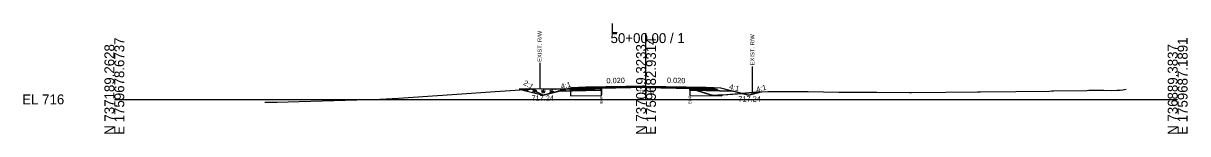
# Model space of a CAD drawing. Extents: x -26 to 4303, y -10 to 9577.
# Drawn here: x 3974.3 to 4302.8, y -9.7 to 21.5 of the extents above; entities that cross this region are included whole.
import ezdxf

# ---------------------------------------------------------------- set-up
doc = ezdxf.new("R2010")
doc.units = 0
for name, color, linetype in [('Default', 7, 'Continuous'), ('Exist CMT Pavement', 7, 'Continuous'), ('Old_Level_2', 7, 'Continuous'), ('Pattern 3', 7, 'Continuous'), ('Prop CMT Conc Surface', 7, 'Continuous'), ('Prop CMT Concrete Structures', 7, 'Continuous'), ('Prop CMT Pvmt Course 1', 7, 'Continuous'), ('Prop CMT Pvmt Course 1 CG', 7, 'Continuous'), ('Prop CMT Pvmt Course 2', 7, 'Continuous'), ('Prop CMT Pvmt Course 2 Wedge', 7, 'Continuous'), ('Prop CMT Pvmt Course 3', 7, 'Continuous'), ('Prop CMT Pvmt Surface', 7, 'Continuous'), ('Prop CMT Pvmt Surface Shoulder', 7, 'Continuous'), ('Prop CMT Pvmt Wedge Surface 1', 7, 'Continuous'), ('Prop CMT Pvmt Wedge Surface 2', 7, 'Continuous'), ('Prop CMT Pvmt Wedge Surface 3', 7, 'Continuous'), ('Prop CMT Shld Paved Course 1', 7, 'Continuous'), ('Prop CMT Shld Paved Course 2', 7, 'Continuous'), ('Prop CMT Shld Paved Course 3', 7, 'Continuous'), ('Prop CMT Slope Grass', 7, 'Continuous'), ('Prop CMT Subgrade Earthwork', 7, 'Continuous'), ('Prop Road Sect_ Recs - UC Shallow (Outline)', 7, 'Continuous'), ('Prop Shade Light', 7, 'Continuous'), ('Prop XS DDE Elevations', 7, 'Continuous'), ('Prop XS Ditch Standard Text', 7, 'Continuous'), ('Prop XS Hydro Elevations', 7, 'Continuous'), ('Prop XS SE Text', 7, 'Continuous'), ('Prop XS Side Slope Text', 7, 'Continuous'), ('Prop XS Wedging', 7, 'Continuous'), ('Scratch_Level_2', 7, 'Continuous')]:
    doc.layers.add(name, color=color, linetype=linetype)

msp = doc.modelspace()

# ---------------------------------------------------------------- linework, layer by layer
at = {"layer": 'Exist CMT Pavement'}
for points in [[(4150, 3.78), (4133, 3.44)], [(4150, 3.78), (4167, 3.44)]]:
    msp.add_lwpolyline(points, dxfattribs=at)
at = {"layer": 'Old_Level_2'}
for p, q in [((4150, 0), (4150, 18.71)), ((4150, 0), (4150, 18.71)), ((4000, 0), (4150, 0)), ((4150, 0), (4300, 0)), ((4000, 0), (4150, 0)), ((4150, 0), (4300, 0))]:
    msp.add_line(p, q, dxfattribs=at)
at = {"layer": 'Pattern 3'}
for p, q in [((4115.87, 2.95), (4116.45, 2.37)), ((4116.04, 2.47), (4116.88, 2.7)), ((4116.39, 2.96), (4116.25, 2.42)), ((4118.03, 2.26), (4119.24, 2.58)), ((4118.2, 2.86), (4119.08, 1.98)), ((4118.77, 2.91), (4118.49, 1.86)), ((4120.04, 1.79), (4119.96, 1.5)), ((4120.39, 2.14), (4121.6, 2.46)), ((4120.55, 2.74), (4121.44, 1.86)), ((4121.14, 2.86), (4120.83, 1.7)), ((4121.79, 1.51), (4121.85, 1.45)), ((4121.96, 2.85), (4121.95, 2.82)), ((4122.39, 1.67), (4122.37, 1.58)), ((4122.75, 2.02), (4123.95, 2.35)), ((4122.91, 2.63), (4123.64, 1.9)), ((4123.51, 2.79), (4123.25, 1.8)), ((4124.35, 2.84), (4124.31, 2.7)), ((4125.26, 2.51), (4125.43, 2.34)), ((4125.87, 2.67), (4125.81, 2.44)), ((4126.73, 2.83), (4126.68, 2.66)), ((4127.18, 2.83), (4127.22, 2.79)), ((4177.37, 1.72), (4177.47, 1.62)), ((4177.92, 1.76), (4177.85, 1.52)), ((4178.26, 1.42), (4178.4, 1.46)), ((4178.76, 1.83), (4178.75, 1.81)), ((4179.71, 1.62), (4179.87, 1.45)), ((4180.31, 1.78), (4180.25, 1.55)), ((4181.19, 2.01), (4181.13, 1.77)), ((4181.53, 2.04), (4181.66, 1.9))]:
    msp.add_line(p, q, dxfattribs=at)
for points in [[(4137.42, 3.3), (4137.41, 2.65), (4128.69, 2.47), (4128.68, 2.83), (4130.46, 2.82), (4131.03, 2.85), (4132.25, 2.92), (4134.24, 3.03), (4135.83, 3.13), (4137.42, 3.3)], [(4114.24, 2.93), (4121, 1.24), (4127.38, 2.83), (4121.38, 2.86), (4116.36, 2.96)], [(4162.41, 3.17), (4162.41, 2.65), (4164.13, 2.62)], [(4182.47, 2.1), (4179, 1.24), (4177.13, 1.7), (4180.99, 2)]]:
    msp.add_lwpolyline(points, close=True, dxfattribs=at)
at = {"layer": 'Prop CMT Conc Surface'}
for points in [[(4137.41, 3.27), (4133, 3.19)], [(4133, 3.19), (4133, 2.98)], [(4133, 2.98), (4137.41, 3.07)], [(4137.41, 3.07), (4137.41, 3.27)], [(4162.41, 3.07), (4162.41, 3.28)], [(4162.41, 3.28), (4167, 3.19)], [(4167, 2.98), (4162.41, 3.07)], [(4167, 3.19), (4167, 2.98)]]:
    msp.add_lwpolyline(points, dxfattribs=at)
at = {"layer": 'Prop CMT Concrete Structures'}
for points in [[(4133, 3.19), (4133, 3.44)], [(4150, 3.65), (4137.41, 3.4)], [(4137.41, 3.4), (4137.41, 3.27)], [(4150, 3.65), (4162.41, 3.4)], [(4162.41, 3.4), (4162.41, 3.28)], [(4167, 3.19), (4167, 3.44)], [(4137.41, 3.27), (4133, 3.19)], [(4162.41, 3.28), (4167, 3.19)]]:
    msp.add_lwpolyline(points, dxfattribs=at)
at = {"layer": 'Prop CMT Pvmt Course 1'}
for points in [[(4137.41, 3.07), (4133, 2.98)], [(4133, 2.98), (4133, 2.64)], [(4133, 2.64), (4137.41, 2.73)], [(4137.41, 2.73), (4137.41, 3.07)], [(4162.41, 3.07), (4167, 2.98)], [(4162.41, 2.74), (4162.41, 3.07)], [(4167, 2.64), (4162.41, 2.74)], [(4167, 2.98), (4167, 2.64)]]:
    msp.add_lwpolyline(points, dxfattribs=at)
at = {"layer": 'Prop CMT Pvmt Course 2'}
for points in [[(4133, 3.44), (4131, 3.4), (4130.74, 3.14)], [(4133, 3.19), (4133, 3.44)], [(4167, 3.44), (4169, 3.4), (4169.26, 3.14)], [(4167, 3.19), (4167, 3.44)], [(4130.74, 3.14), (4133, 3.19)], [(4169.26, 3.14), (4167, 3.19)]]:
    msp.add_lwpolyline(points, dxfattribs=at)
at = {"layer": 'Prop CMT Pvmt Course 2 Wedge'}
msp.add_line((4117.68, 2.9), (4121, 1.24), dxfattribs=at)
for points in [[(4131, 3.4), (4129, 3.24), (4121, 1.24)], [(4169, 3.4), (4171, 3.24), (4179, 1.24), (4182.47, 2.1)]]:
    msp.add_lwpolyline(points, dxfattribs=at)
at = {"layer": 'Prop CMT Pvmt Course 3'}
for points in [[(4133, 3.19), (4130.74, 3.14), (4130.53, 2.93)], [(4130.53, 2.93), (4133, 2.98)], [(4133, 2.98), (4133, 3.19)], [(4167, 3.19), (4169.26, 3.14), (4169.47, 2.93)], [(4167, 2.98), (4167, 3.19)], [(4169.47, 2.93), (4167, 2.98)]]:
    msp.add_lwpolyline(points, dxfattribs=at)
at = {"layer": 'Prop CMT Pvmt Surface'}
for points in [[(4150, 3.53), (4133, 3.19)], [(4133, 3.19), (4133, 3.44)], [(4150, 3.53), (4167, 3.19)], [(4167, 3.19), (4167, 3.44)]]:
    msp.add_lwpolyline(points, dxfattribs=at)
at = {"layer": 'Prop CMT Pvmt Surface Shoulder'}
for points in [[(4137.42, 3.3), (4137.44, 3.3), (4137.93, 3.32), (4138.07, 3.32), (4138.18, 3.34), (4138.84, 3.35), (4140.18, 3.39), (4140.57, 3.4), (4141.63, 3.42), (4143.07, 3.44), (4144.06, 3.47), (4145.57, 3.53), (4146.49, 3.54), (4148.07, 3.56), (4148.38, 3.57), (4148.89, 3.57), (4149.15, 3.57), (4149.86, 3.58), (4150, 3.58)], [(4150, 3.58), (4150.31, 3.59), (4150.48, 3.59), (4150.57, 3.59), (4151.35, 3.57), (4153.07, 3.54), (4153.79, 3.52), (4155.58, 3.47), (4156.22, 3.45), (4158.08, 3.4), (4158.74, 3.38), (4159.85, 3.34), (4160.97, 3.3), (4161.48, 3.27), (4162.26, 3.22), (4162.41, 3.17)]]:
    msp.add_lwpolyline(points, dxfattribs=at)
at = {"layer": 'Prop CMT Pvmt Wedge Surface 1'}
for p, q in [((4133.02, 2.52), (4125.53, 2.37)), ((4137.41, 2.61), (4133.02, 2.52)), ((4162.41, 2.61), (4166.98, 2.52)), ((4166.98, 2.52), (4174.47, 2.37))]:
    msp.add_line(p, q, dxfattribs=at)
for points in [[(4137.41, 2.61), (4137.42, 3.3)], [(4162.41, 2.61), (4162.41, 3.17)]]:
    msp.add_lwpolyline(points, dxfattribs=at)
at = {"layer": 'Prop CMT Pvmt Wedge Surface 2'}
for points in [[(4137.41, 3.4), (4137.44, 3.4), (4137.93, 3.41), (4138.07, 3.41), (4138.18, 3.41), (4138.84, 3.43), (4140.18, 3.45), (4140.57, 3.46), (4141.63, 3.48), (4143.07, 3.51), (4144.06, 3.53), (4145.57, 3.56), (4146.49, 3.58), (4148.07, 3.61), (4148.38, 3.62), (4148.89, 3.63), (4149.15, 3.63), (4149.86, 3.65), (4150, 3.65)], [(4150, 3.58), (4149.86, 3.58), (4149.15, 3.57), (4148.89, 3.57), (4148.38, 3.57), (4148.07, 3.56), (4146.49, 3.54), (4145.57, 3.53), (4144.06, 3.47), (4143.07, 3.44), (4141.63, 3.42), (4140.57, 3.4), (4140.18, 3.39), (4138.84, 3.35), (4138.18, 3.34), (4138.07, 3.32), (4137.93, 3.32), (4137.44, 3.3), (4137.41, 3.3)], [(4137.41, 3.3), (4137.41, 3.4)], [(4150, 3.65), (4150, 3.58)], [(4150, 3.65), (4150.31, 3.64), (4150.48, 3.64), (4150.57, 3.64), (4151.35, 3.62), (4153.07, 3.59), (4153.79, 3.57), (4155.58, 3.54), (4156.22, 3.53), (4158.08, 3.49), (4158.74, 3.48), (4159.85, 3.45), (4160.97, 3.43), (4161.48, 3.42), (4162.26, 3.41), (4162.41, 3.4)], [(4162.41, 3.28), (4162.26, 3.28), (4161.48, 3.3), (4160.97, 3.31), (4160.9, 3.31), (4159.85, 3.34), (4158.74, 3.38), (4158.08, 3.4), (4156.22, 3.45), (4155.58, 3.47), (4153.79, 3.52), (4153.07, 3.54), (4151.35, 3.57), (4150.57, 3.59), (4150.48, 3.59), (4150.31, 3.59), (4150, 3.58)], [(4162.41, 3.4), (4162.41, 3.28)]]:
    msp.add_lwpolyline(points, dxfattribs=at)
at = {"layer": 'Prop CMT Pvmt Wedge Surface 3'}
for points in [[(4162.41, 3.17), (4162.26, 3.22), (4161.48, 3.27), (4160.97, 3.3), (4160.9, 3.31)], [(4160.9, 3.31), (4160.97, 3.31)], [(4160.97, 3.31), (4161.48, 3.3), (4162.26, 3.28), (4162.41, 3.28)], [(4162.41, 3.28), (4162.41, 3.17)]]:
    msp.add_lwpolyline(points, dxfattribs=at)
at = {"layer": 'Prop CMT Shld Paved Course 1'}
for points in [[(4133, 2.98), (4133, 3.44)], [(4150, 3.32), (4133, 2.98)], [(4150, 3.32), (4167, 2.98)], [(4167, 2.98), (4167, 3.44)]]:
    msp.add_lwpolyline(points, dxfattribs=at)
at = {"layer": 'Prop CMT Shld Paved Course 2'}
for points in [[(4133, 3.44), (4131, 3.4)], [(4167, 3.44), (4169, 3.4)]]:
    msp.add_lwpolyline(points, dxfattribs=at)
at = {"layer": 'Prop CMT Shld Paved Course 3'}
for points in [[(4150, 3.78), (4133, 3.44)], [(4133, 3.44), (4133, 3.19)], [(4137.41, 3.4), (4150, 3.65)], [(4137.41, 3.27), (4137.41, 3.4)], [(4150, 3.53), (4150, 3.78)], [(4150, 3.78), (4167, 3.44)], [(4150, 3.65), (4150, 3.53), (4150, 3.53)], [(4162.41, 3.4), (4150, 3.65)], [(4162.41, 3.28), (4162.41, 3.4)], [(4167, 3.44), (4167, 3.19)], [(4133, 3.19), (4137.41, 3.27)], [(4167, 3.19), (4162.41, 3.28)]]:
    msp.add_lwpolyline(points, dxfattribs=at)
at = {"layer": 'Prop CMT Slope Grass'}
msp.add_lwpolyline([(4042.46, -0.8), (4045.91, -0.76), (4052.14, -0.57), (4074.87, 0.11), (4080.19, 0.34), (4084.27, 0.61), (4098.02, 1.59), (4106.01, 2.1), (4120.16, 3.07), (4125.39, 3.01), (4132.53, 3.03), (4137.44, 3.3), (4138.18, 3.34), (4138.84, 3.35), (4140.18, 3.39), (4140.57, 3.4), (4141.63, 3.42), (4143.07, 3.44), (4144.06, 3.47), (4145.57, 3.53), (4146.49, 3.54), (4148.07, 3.56), (4148.38, 3.57), (4149.15, 3.57), (4149.86, 3.58), (4150.57, 3.59), (4151.35, 3.57), (4153.07, 3.54), (4153.79, 3.52), (4155.58, 3.47), (4156.22, 3.45), (4158.08, 3.4), (4158.74, 3.38), (4159.85, 3.34), (4160.97, 3.3), (4161.48, 3.27), (4162.26, 3.22), (4168.19, 1.32), (4169.12, 1.08), (4180.99, 2), (4184.35, 2.24), (4185.99, 2.21), (4194.36, 2.28), (4195.72, 2.24), (4204.36, 2.02), (4213.52, 2.07), (4214.37, 2.06), (4215.17, 2.06), (4224.37, 1.94), (4224.9, 1.93), (4234.63, 2.09), (4243.57, 2.1), (4244.41, 2.1), (4254.39, 2.24), (4263.82, 2.37), (4264.39, 2.38), (4265, 2.39), (4274.4, 2.56), (4274.95, 2.58), (4279.19, 2.58), (4281.45, 2.54), (4282.86, 2.57), (4283.82, 2.57), (4284.51, 2.7), (4285.04, 2.79), (4285.46, 2.89)], dxfattribs=at)
at = {"layer": 'Prop CMT Subgrade Earthwork'}
for points in [[(4133, 2.98), (4130.53, 2.93), (4130.03, 2.92), (4129.69, 2.58)], [(4129.69, 2.58), (4133, 2.64)], [(4133, 2.64), (4133, 2.98)], [(4167, 2.98), (4169.47, 2.93), (4169.97, 2.92), (4170.31, 2.58)], [(4167, 2.64), (4167, 2.98)], [(4170.31, 2.58), (4167, 2.64)]]:
    msp.add_lwpolyline(points, dxfattribs=at)
at = {"layer": 'Prop Road Sect_ Recs - UC Shallow (Outline)'}
for points in [[(4128.72, 0.97), (4137.44, 1.15), (4137.41, 2.64), (4128.69, 2.47)], [(4162.38, 1.15), (4171.36, 0.97), (4171.37, 1.26), (4169.14, 1.09), (4168.19, 1.32), (4164.13, 2.62), (4162.41, 2.65)]]:
    msp.add_lwpolyline(points, close=True, dxfattribs=at)
at = {"layer": 'Prop Shade Light'}
for p, q in [((4129.69, 2.49), (4128.69, 2.47)), ((4128.69, 2.47), (4128.72, 0.97)), ((4128.72, 0.97), (4137.44, 1.15)), ((4137.44, 1.15), (4137.41, 2.65)), ((4162.41, 2.65), (4162.38, 1.15)), ((4162.38, 1.15), (4171.36, 0.97)), ((4164.13, 2.62), (4164.13, 2.62)), ((4171.37, 1.26), (4170.26, 1.17)), ((4171.36, 0.97), (4171.37, 1.26))]:
    msp.add_line(p, q, dxfattribs=at)
for points in [[(4137.41, 2.65), (4133, 2.56), (4129.69, 2.49)], [(4164.13, 2.62), (4164.13, 2.62), (4162.41, 2.65)], [(4170.26, 1.17), (4169.14, 1.09), (4168.19, 1.32), (4164.13, 2.62)]]:
    msp.add_lwpolyline(points, dxfattribs=at)
at = {"layer": 'Prop XS DDE Elevations'}
for points in [[(4128.12, 3.02), (4125.53, 2.37), (4133.02, 2.52), (4137.41, 2.61), (4137.42, 3.3), (4132.53, 3.03)], [(4138.07, 3.32), (4138.18, 3.34), (4137.44, 3.3), (4137.93, 3.32)], [(4148.38, 3.57), (4149.15, 3.57), (4148.89, 3.57)], [(4149.86, 3.58), (4150.57, 3.59), (4150.48, 3.59), (4150.31, 3.59), (4150, 3.58)], [(4128.12, 3.02), (4125.53, 2.37), (4121, 1.24), (4117.68, 2.9), (4120.16, 3.07), (4125.39, 3.01)], [(4162.41, 2.61), (4162.41, 3.17), (4164.27, 2.57)], [(4168.19, 1.32), (4169.12, 1.08), (4177.13, 1.7), (4174.47, 2.37), (4166.98, 2.52), (4164.27, 2.57)], [(4177.13, 1.7), (4179, 1.24), (4182.47, 2.1), (4180.99, 2)]]:
    msp.add_lwpolyline(points, close=True, dxfattribs=at)
at = {"layer": 'Prop XS Ditch Standard Text'}
for p, q in [((4120, 10.29), (4120, 2.89)), ((4180, 9.32), (4180, 1.92)), ((4137.41, 3.3), (4137.41, 1.25)), ((4162.41, 3.17), (4162.41, 1.12))]:
    msp.add_line(p, q, dxfattribs=at)
at = {"layer": 'Prop XS Wedging'}
for p, q in [((4137.42, 3.3), (4137.42, 3.64)), ((4137.42, 3.4), (4137.42, 3.3)), ((4162.41, 3.17), (4162.41, 3.52)), ((4162.41, 3.17), (4162.41, 3.4)), ((4162.41, 3.17), (4162.41, 3.17))]:
    msp.add_line(p, q, dxfattribs=at)
for points in [[(4150, 3.65), (4133, 3.31)], [(4150, 3.65), (4150, 3.65), (4137.42, 3.4)], [(4137.42, 3.3), (4137.44, 3.3), (4138.18, 3.34), (4138.84, 3.35), (4140.18, 3.39), (4140.57, 3.4), (4141.63, 3.42), (4143.07, 3.44), (4144.06, 3.47), (4145.57, 3.53), (4146.49, 3.54), (4148.07, 3.56), (4148.38, 3.57), (4149.15, 3.57), (4149.86, 3.58), (4150.57, 3.59), (4151.35, 3.57), (4153.07, 3.54), (4153.79, 3.52), (4155.58, 3.47), (4156.22, 3.45), (4158.08, 3.4), (4158.74, 3.38), (4159.85, 3.34), (4160.97, 3.3), (4161.48, 3.27), (4162.26, 3.22), (4162.41, 3.17)], [(4150, 3.65), (4167, 3.31)], [(4162.41, 3.4), (4150, 3.65), (4150, 3.65)]]:
    msp.add_lwpolyline(points, dxfattribs=at)
at = {"layer": 'Scratch_Level_2'}
for p, q in [((4130.19, 2.82), (4130.13, 2.59)), ((4130.53, 2.82), (4130.71, 2.64)), ((4132.02, 2.8), (4132.5, 2.94)), ((4132.61, 2.94), (4132.53, 2.63)), ((4132.64, 2.94), (4132.94, 2.64)), ((4134.37, 2.69), (4135.58, 3.01)), ((4134.76, 3.06), (4135.14, 2.69)), ((4135.04, 3.08), (4134.93, 2.68)), ((4136.89, 3.17), (4137.33, 2.73)), ((4137.42, 3.04), (4137.33, 2.73)), ((4137.34, 2.73), (4137.41, 2.75))]:
    msp.add_line(p, q, dxfattribs=at)

# ---------------------------------------------------------------- texts
at = {"layer": 'Default'}
msp.add_text('-', height=0.0001, dxfattribs=at).set_placement((4000, 0))
at = {"layer": 'Old_Level_2'}
for s, p in [('L', (4140, 18.71)), ('L', (4140, 18.71)), ('50+00.00 / 1', (4140, 15.91)), ('50+00.00 / 1', (4140, 15.91)), ('EL 716', (3974, -1.4)), ('EL 716', (3974, -1.4))]:
    msp.add_text(s, height=2.8, dxfattribs=at).set_placement(p)
for s, p in [('E 1759678.6737', (4002.8, -10)), ('E 1759678.6737', (4002.8, -10)), ('E 1759682.9314', (4152.8, -10)), ('E 1759682.9314', (4152.8, -10)), ('E 1759687.1891', (4302.8, -10)), ('E 1759687.1891', (4302.8, -10)), ('N 737189.2628', (4000, -10)), ('N 737189.2628', (4000, -10)), ('N 737039.3233', (4150, -10)), ('N 737039.3233', (4150, -10)), ('N 736889.3837', (4300, -10)), ('N 736889.3837', (4300, -10))]:
    msp.add_text(s, height=2.8, rotation=90, dxfattribs=at).set_placement(p)
at = {"layer": 'Prop CMT Pvmt Course 1 CG'}
msp.add_text('719.58', height=1, dxfattribs=at).set_placement((4147.98, 1.58))
at = {"layer": 'Prop XS Ditch Standard Text'}
for s, height, p in [('EXIST. R/W', 1.181, (4120.59, 10.59)), ('EXIST. R/W', 1.181, (4180.59, 9.63)), ('EOP', 0.787, (4137.81, -1.15)), ('EOP', 0.787, (4162.8, -1.28))]:
    msp.add_text(s, height=height, rotation=90, dxfattribs=at).set_placement(p)
at = {"layer": 'Prop XS Hydro Elevations'}
for p in [(4117.7, -0.38), (4176.07, -0.61)]:
    msp.add_text('717.24', height=1.5, dxfattribs=at).set_placement(p)
at = {"layer": 'Prop XS SE Text'}
for rotation, p in [(1.1458, (4138.86, 4.55)), (358.8542, (4155.9, 4.66))]:
    msp.add_text('0.020', height=1.5, rotation=rotation, dxfattribs=at).set_placement(p)
at = {"layer": 'Prop XS Side Slope Text'}
for s, rotation, p in [('2:1', 330.1407, (4115.23, 4.24)), ('4:1', 14.0362, (4126.17, 2.91)), ('4:1', 345.9638, (4173.36, 2.95)), ('4:1', 14.0362, (4181.31, 2.07))]:
    msp.add_text(s, height=1.5, rotation=rotation, dxfattribs=at).set_placement(p)

doc.saveas('drawing.dxf')
